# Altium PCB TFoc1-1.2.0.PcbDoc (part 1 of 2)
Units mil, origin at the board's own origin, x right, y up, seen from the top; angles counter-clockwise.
Board outline 1584.83 x 1584.83 mil, 4 copper layers (Top Layer, GND, SIGNAL, Bottom Layer), stack 61.85 mil thick; 89 components, 88 nets, 364 pads, 205 vias.
Unrouted connection lines stored in the file: 1.
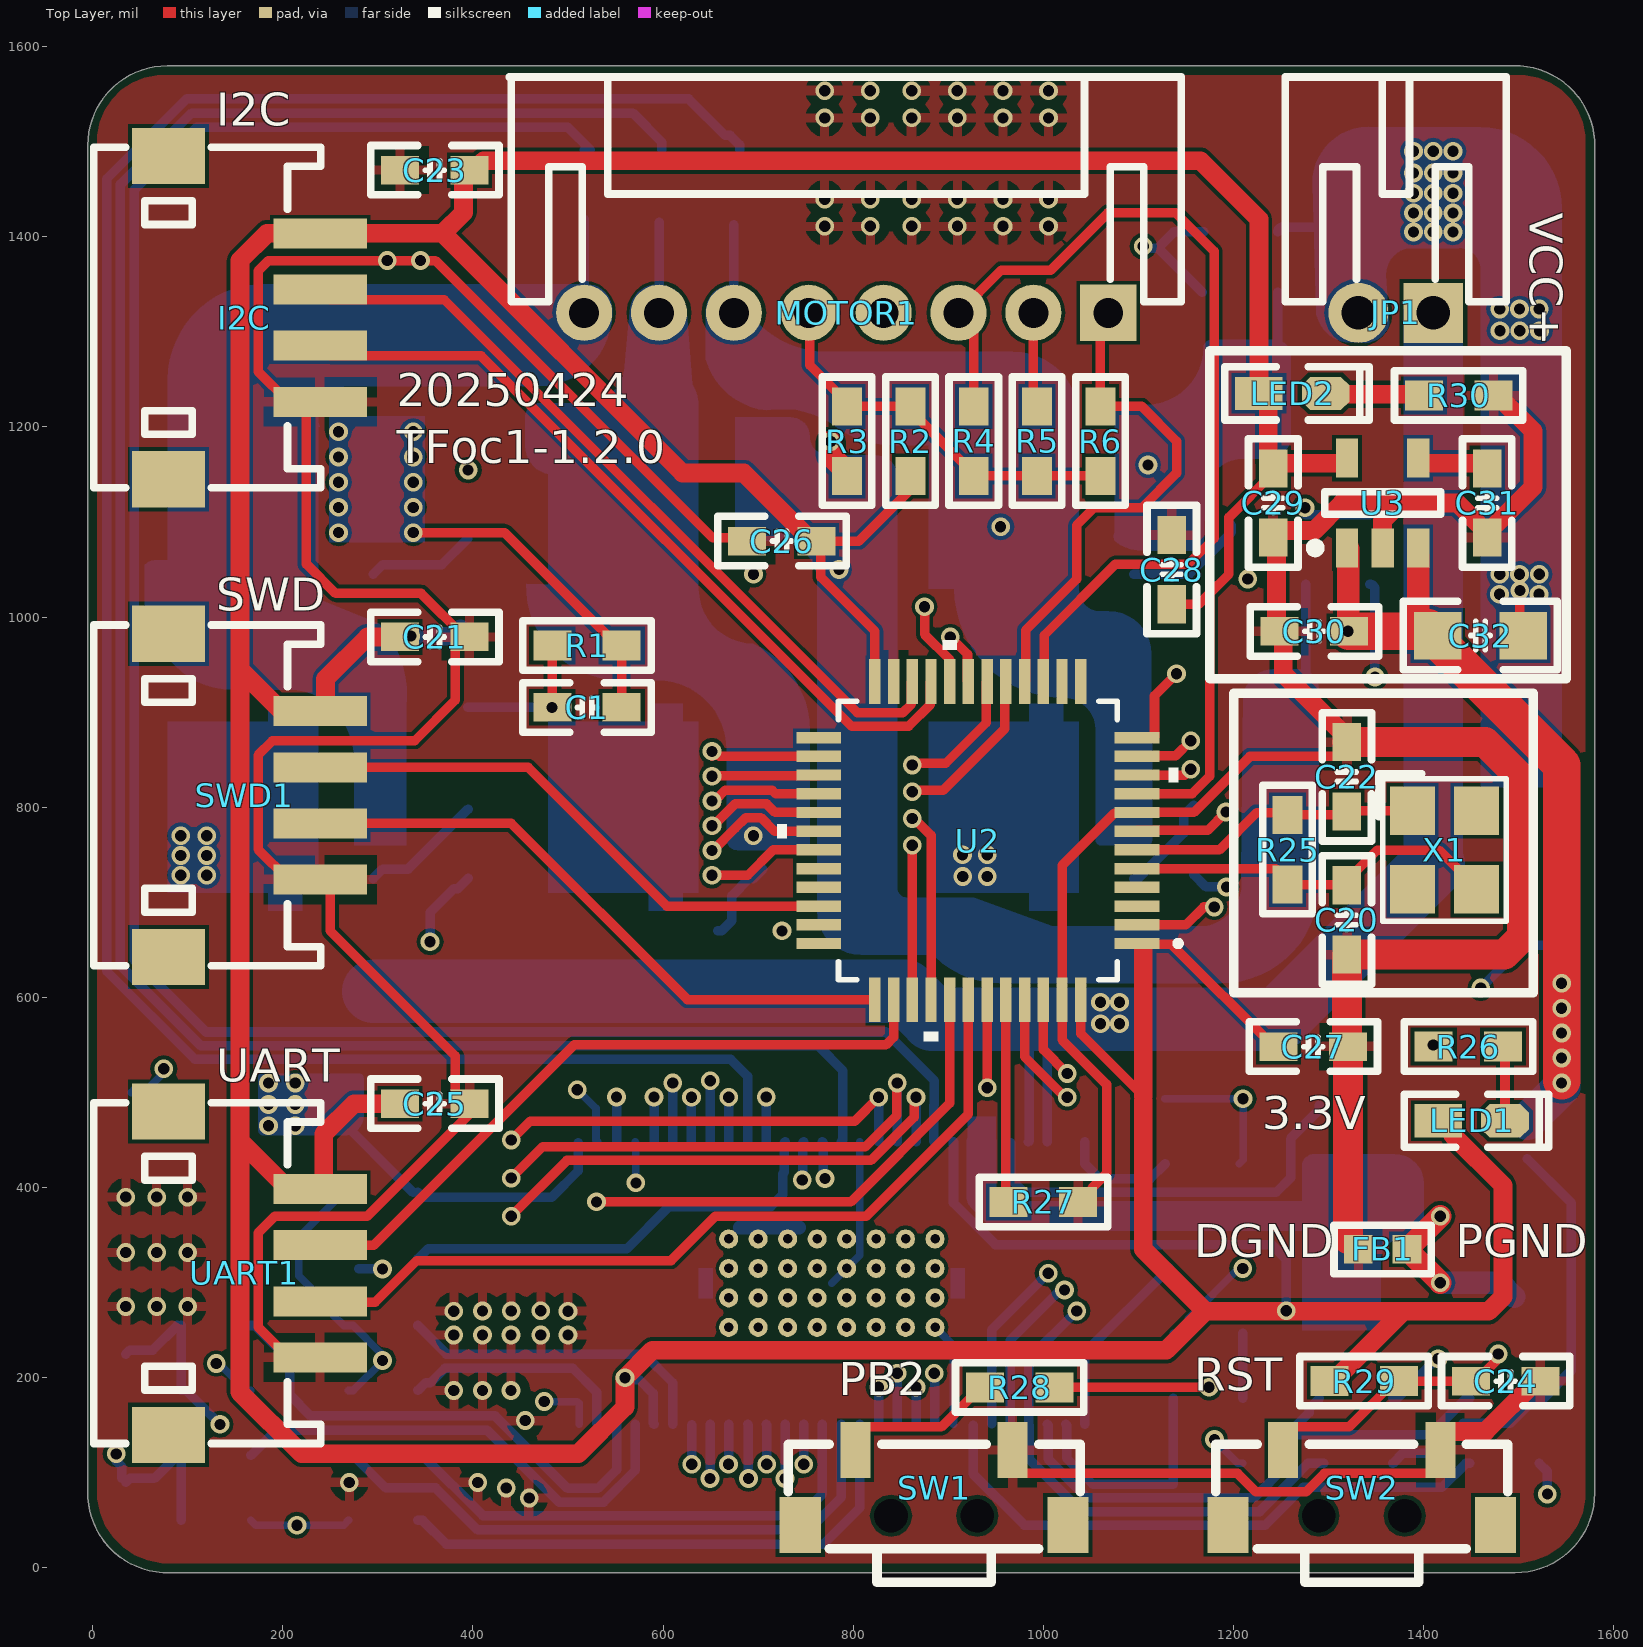
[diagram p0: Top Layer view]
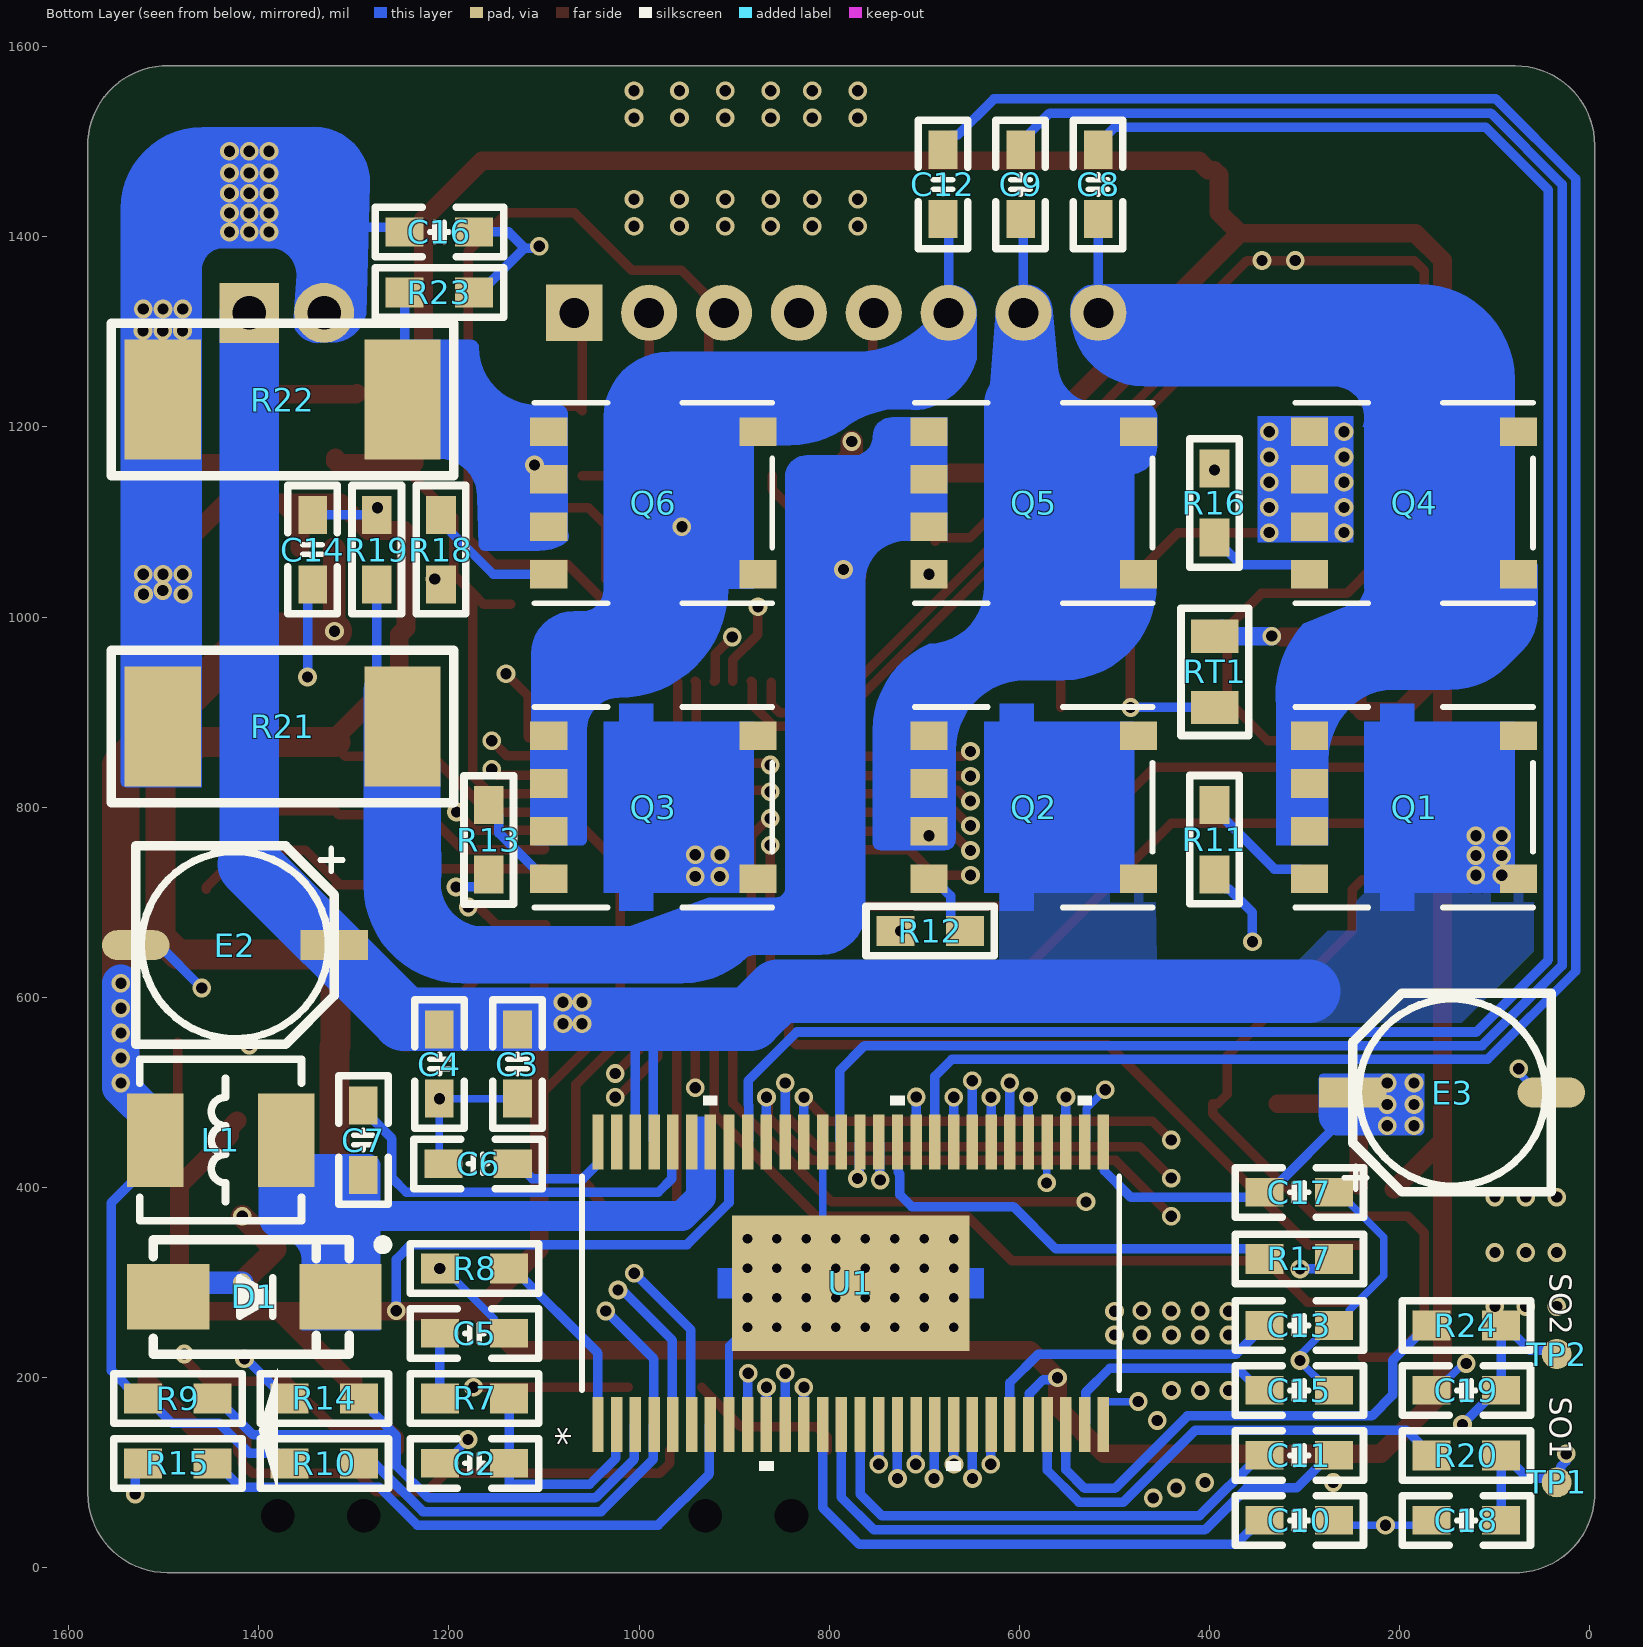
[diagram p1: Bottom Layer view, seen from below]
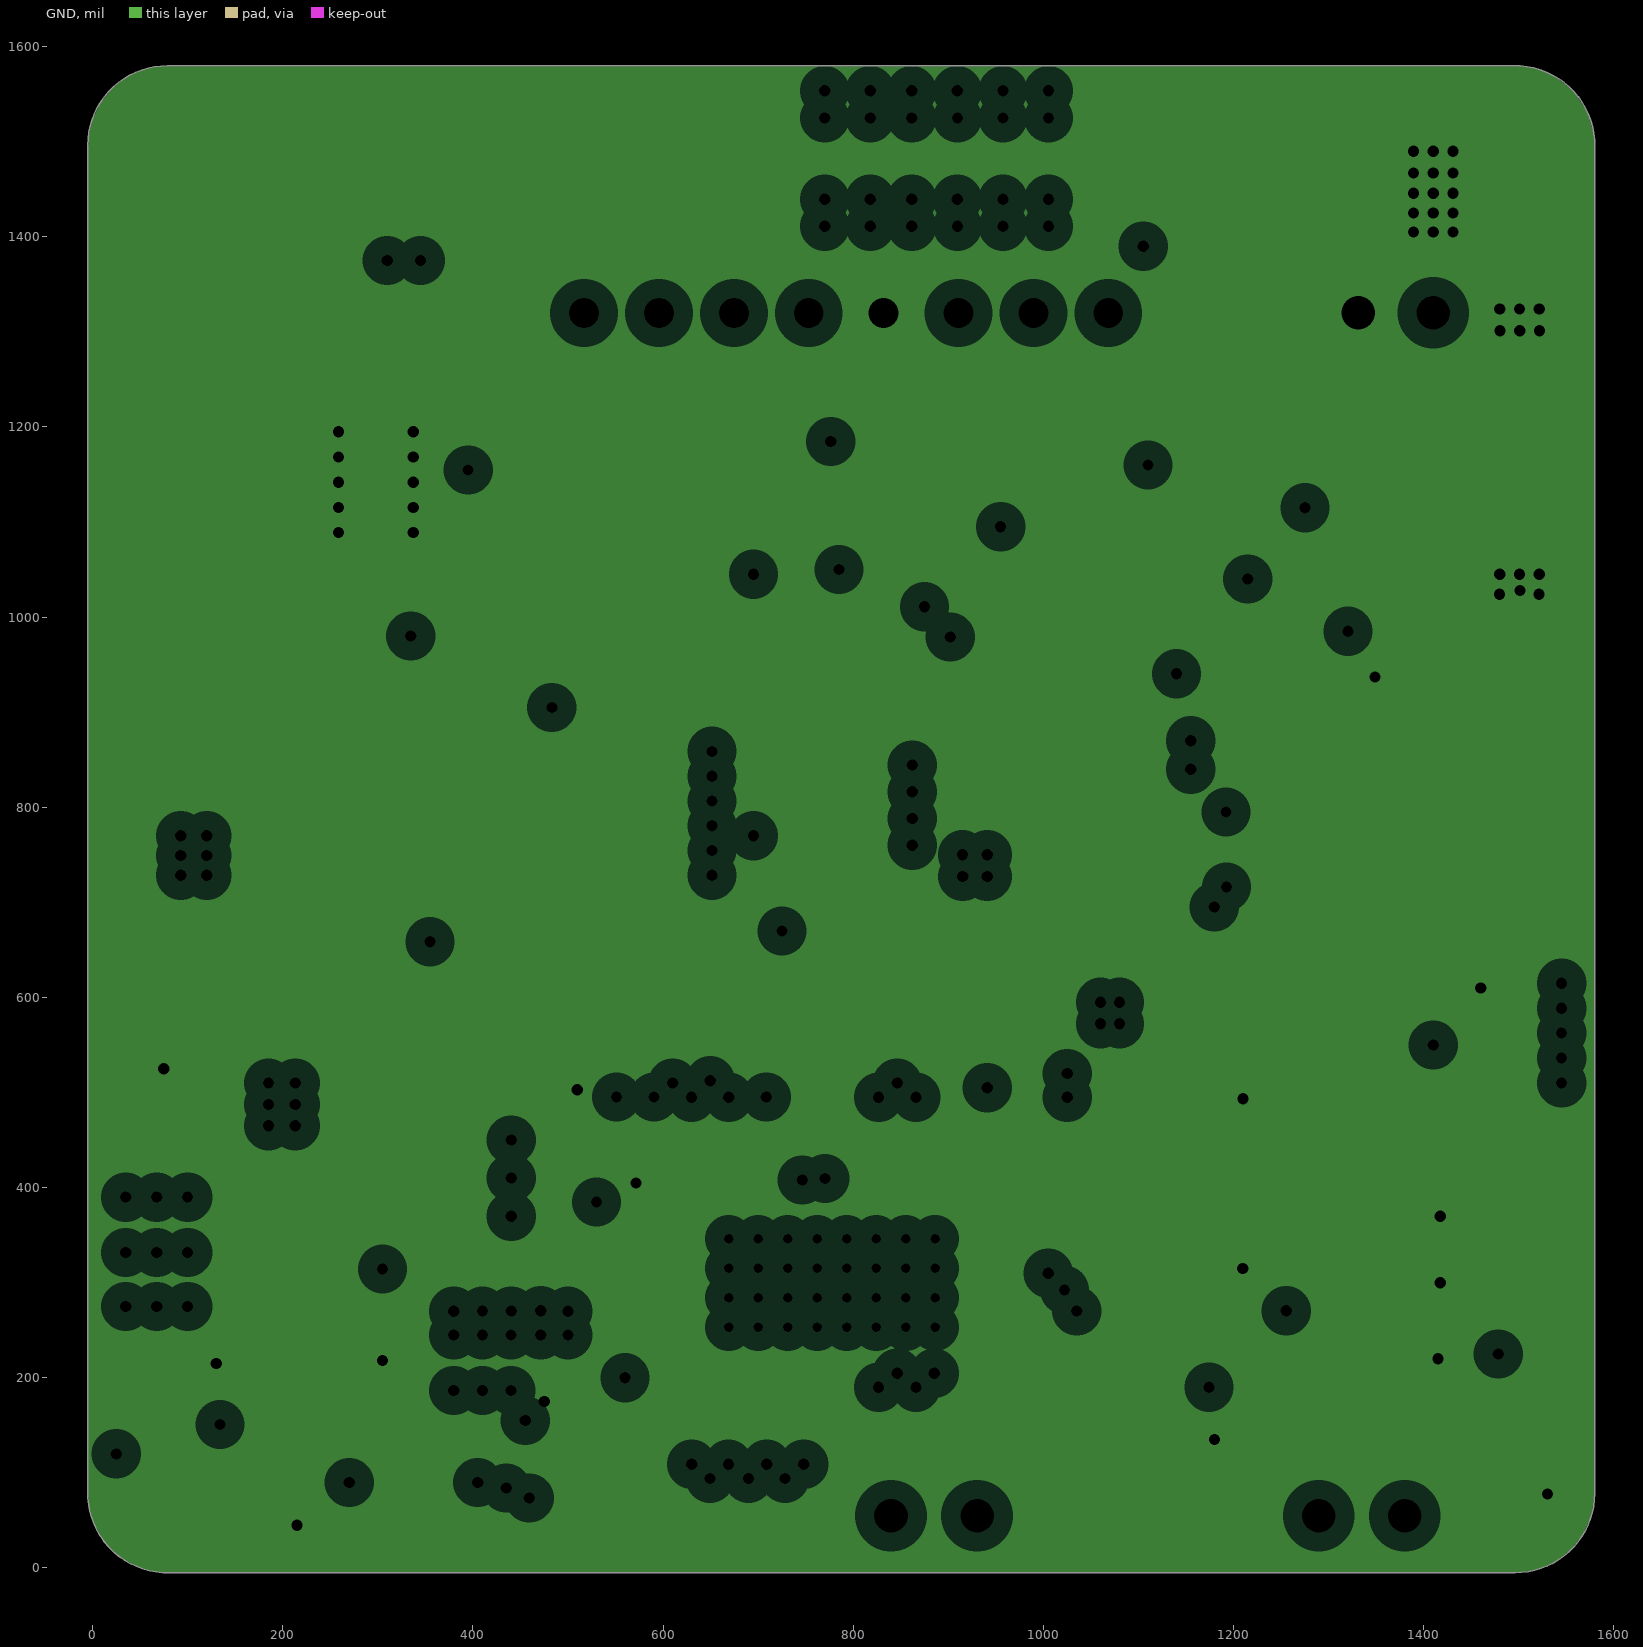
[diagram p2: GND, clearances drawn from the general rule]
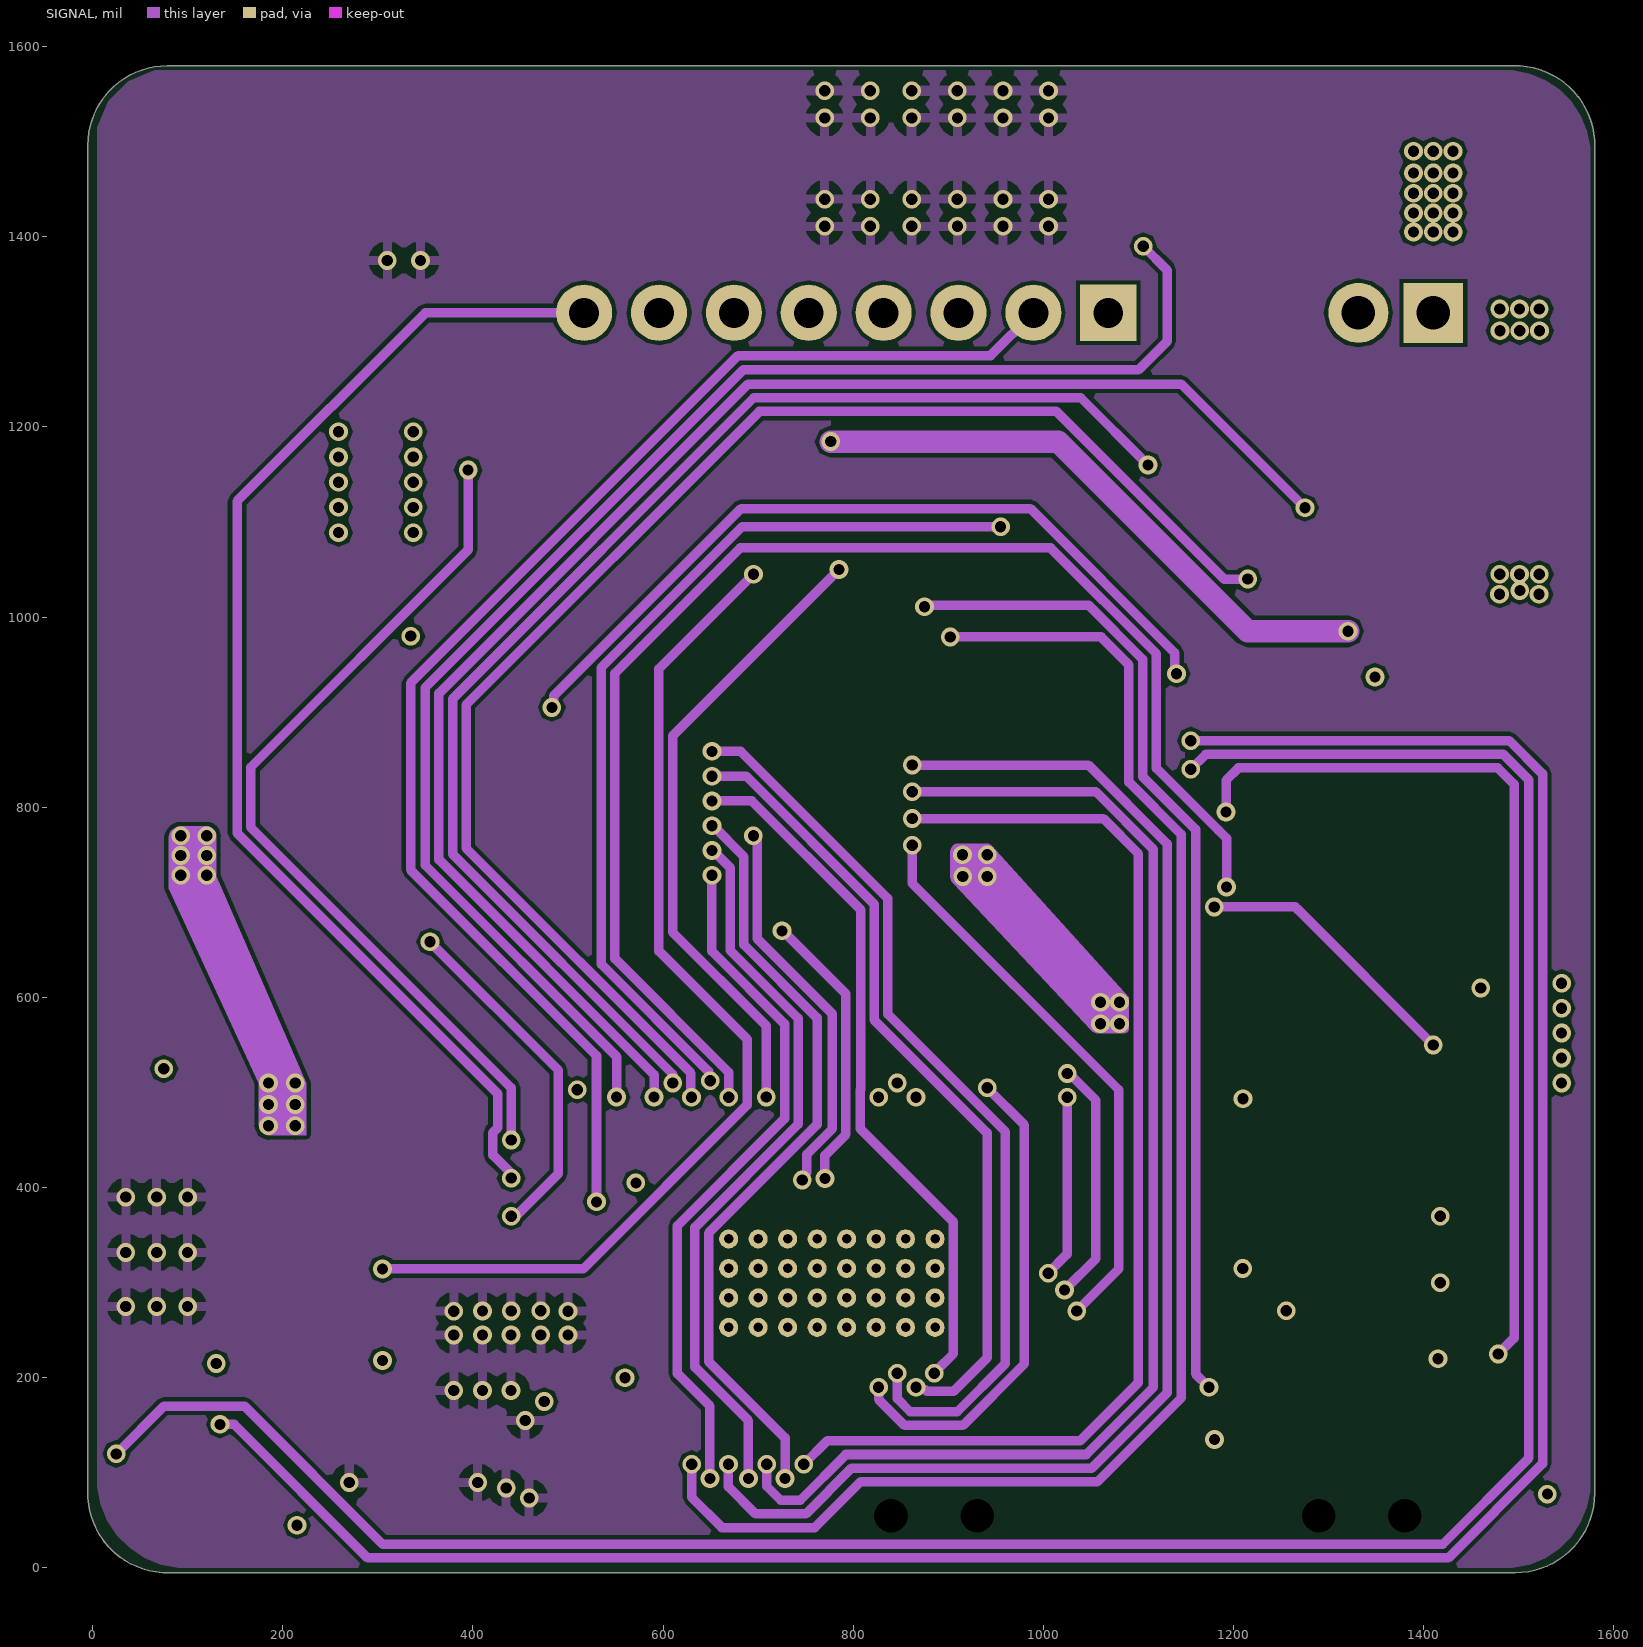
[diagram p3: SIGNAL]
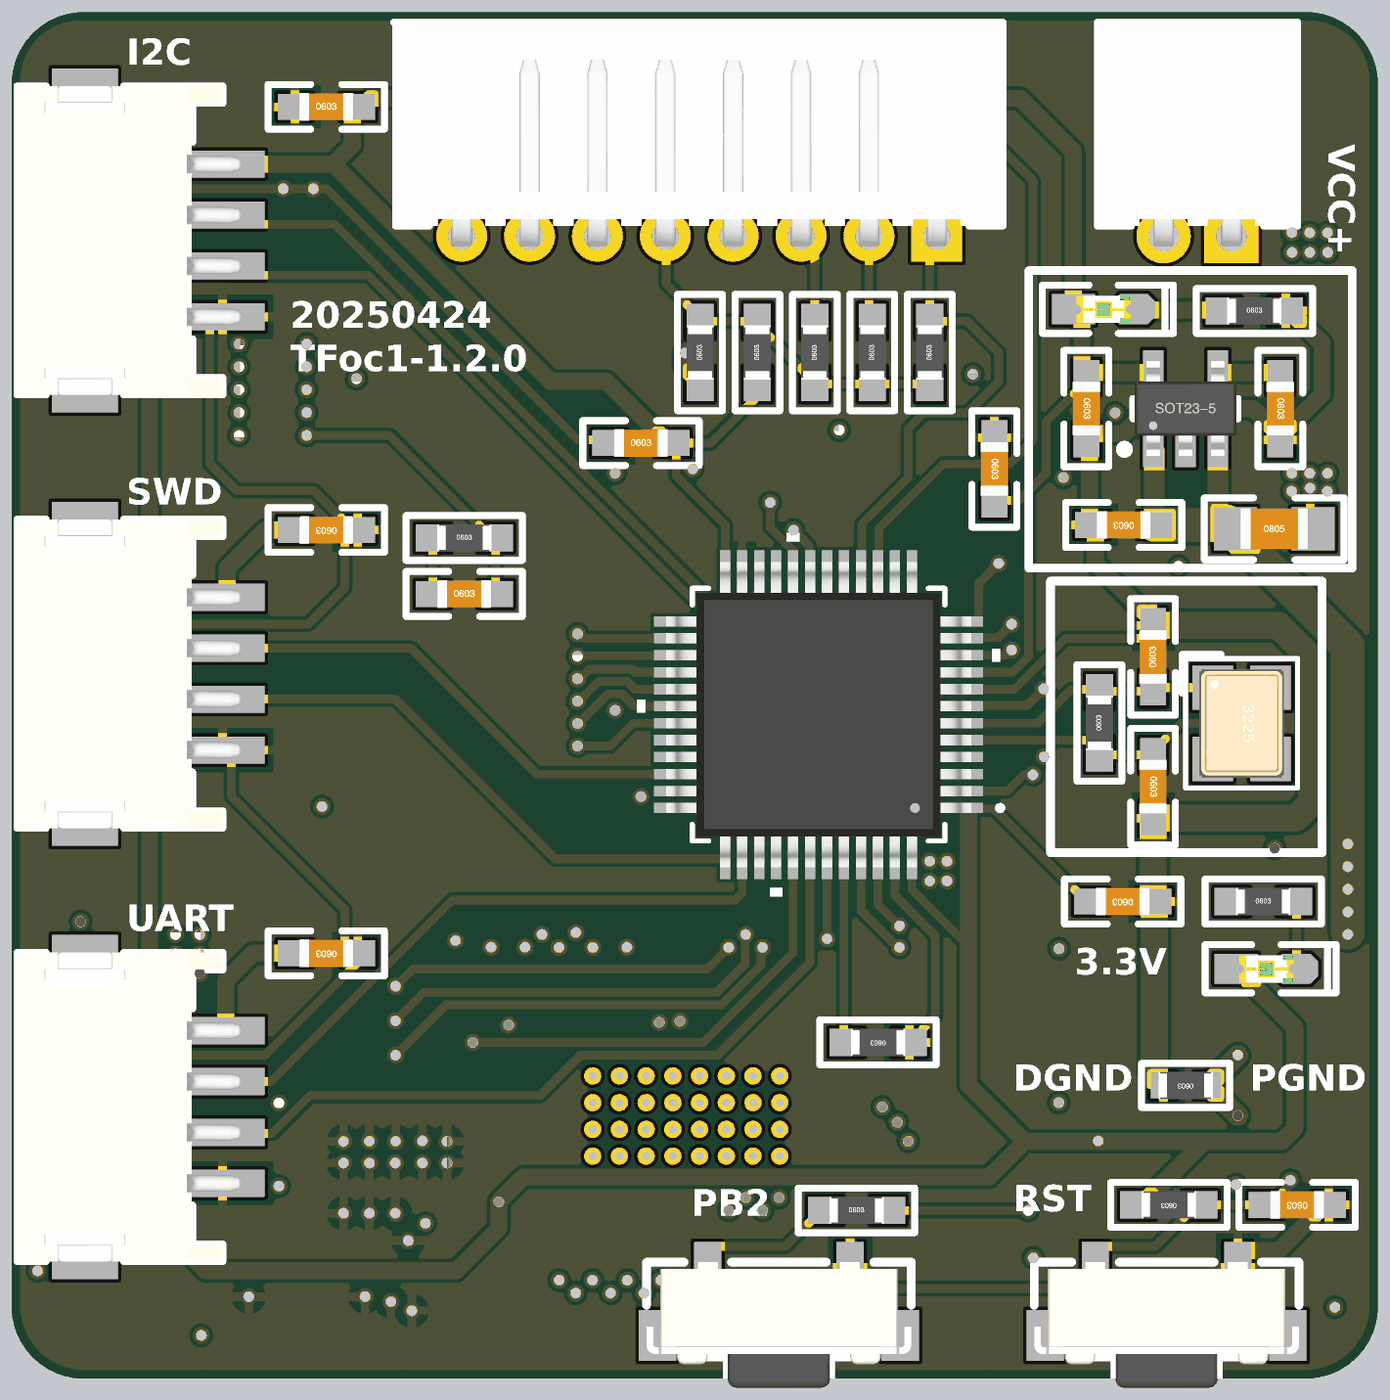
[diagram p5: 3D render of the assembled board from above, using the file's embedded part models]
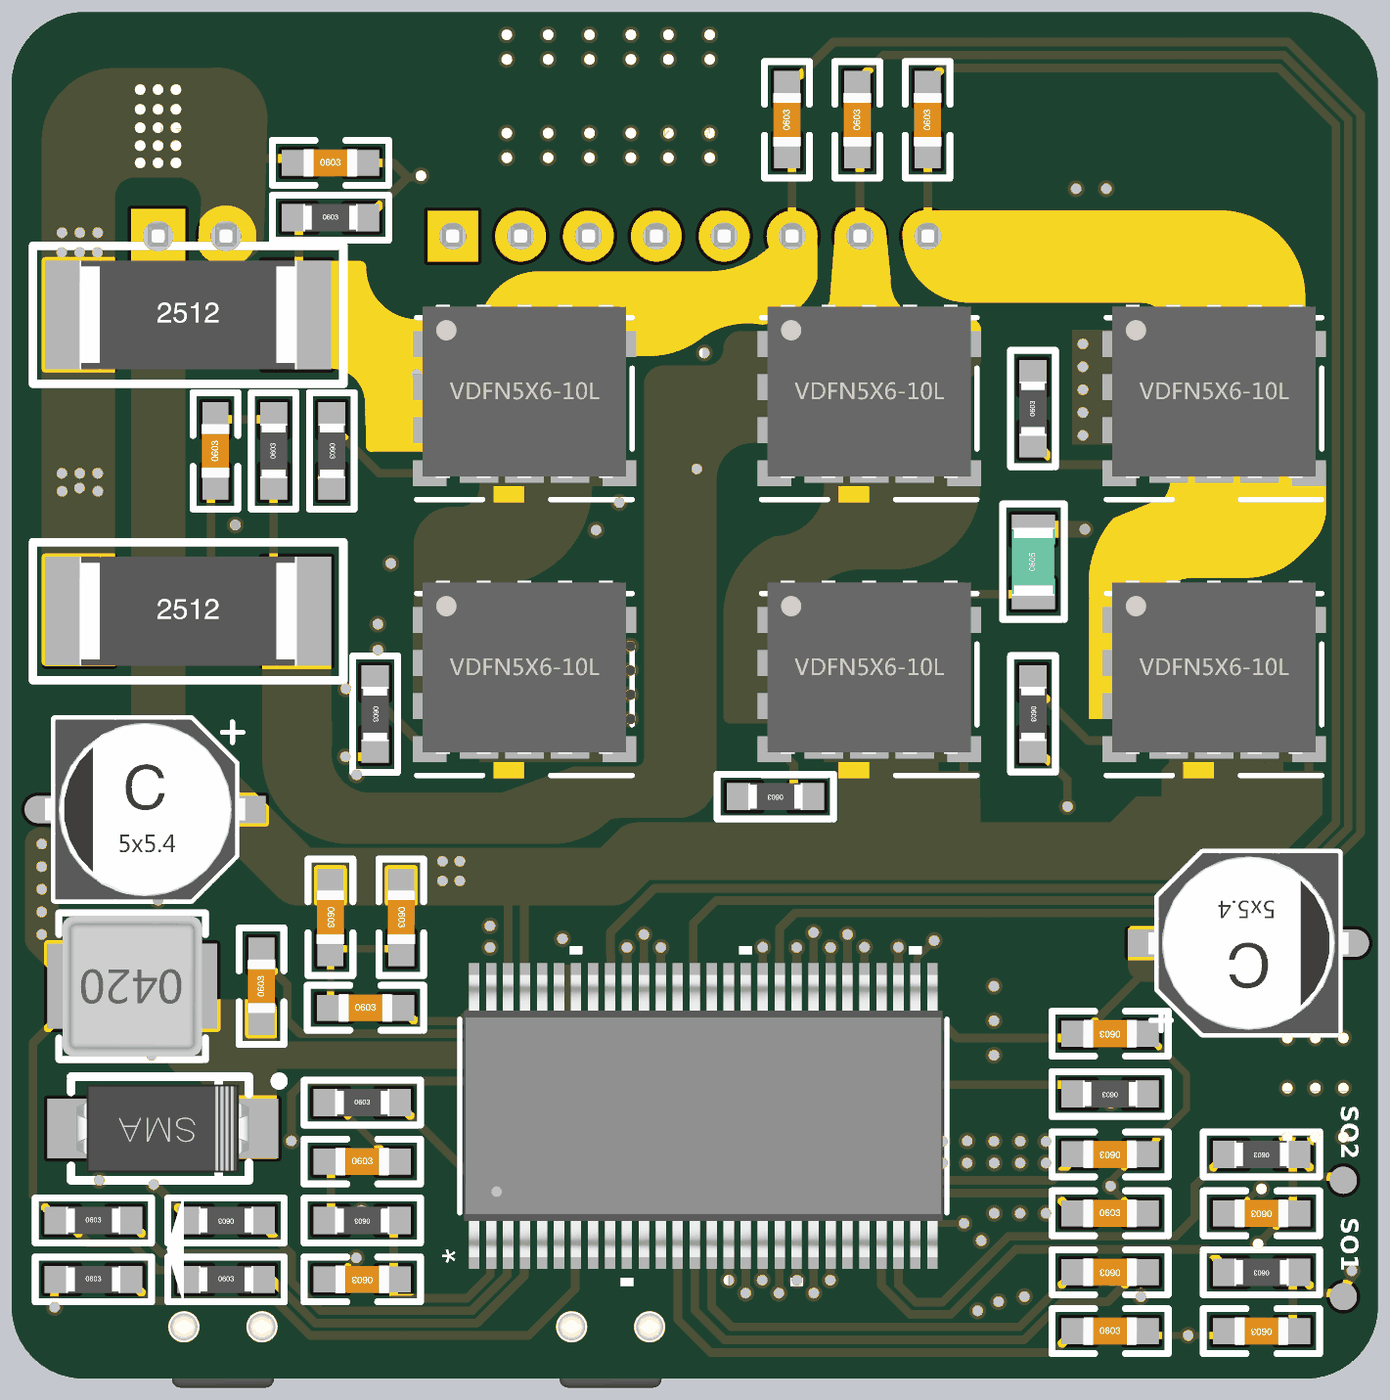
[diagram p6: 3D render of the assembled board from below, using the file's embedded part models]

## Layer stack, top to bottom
Top Solder: solder mask 0.4, Solder Resist, Dk 3.5
Top Layer: signal copper 1.3778
Dielectric 3: prepreg 7.874, PP-JLC7628, Dk 4.5
GND: plane copper 0.7086, net GND
Dielectric 1: core 41.9291, Core-JLC7628, Dk 4.6
SIGNAL: signal copper 0.7086
Dielectric 2: prepreg 7.874, PP-JLC7628, Dk 4.5
Bottom Layer: signal copper 1.3778
Bottom Solder: solder mask 0.4, Solder Resist, Dk 3.5

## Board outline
73.8,-4.87 cw(c78.74,78.74) -4.87,73.8 cw(c0,75) -5.02,75 -5.02,1496.06 cw(c78.74,1496.06) 78.74,1579.82 cw(c78.74,1574.8) 78.77,1579.82 1500.2,1579.82 cw(c1500.2,1574.8) 1501.52,1579.64 cw(c1496.06,1496.06) 1579.64,1501.52 cw(c1574.8,1500.2) 1579.82,1500.2 1579.82,78.74 cw(c1496.06,78.74) 1496.06,-5.01 75,-5.01 cw(c75,0)

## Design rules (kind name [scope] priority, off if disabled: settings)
Clearance [All] p1: gap=4 ignorepadtopadclearanceinfootprint=TRUE
PlaneClearance [All] p1: clearance=20
PlaneConnect [All] p1: planeconnectstyle=Direct reliefexpansion=5 reliefentries=4 reliefconductorwidth=10 reliefairgap=5
PolygonConnect [All] p1: connectstyle=Relief reliefconductorwidth=10 reliefentries=4 polygonreliefangle="90 Angle" airgapwidth=10
RoutingVias [All] p1: holewidth=11.81 width=19.68 viastyle="Through Hole" minholewidth=7.87 minwidth=17.72 maxholewidth=11.81 maxwidth=19.68
ShortCircuit [All] p1: allowed=TRUE
SolderMaskExpansion [All] p1: expansion=4
UnRoutedNet [All] p1: checkbadconnections=TRUE
Width [All] p1: maxlimit=196.85 minlimit=0.39 preferedwidth=10
26 further rules are at their usual default settings.

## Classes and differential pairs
component class U_POWER: C29 C30 C31 FB1 JP1 LED2 R30 U3
component class MAIN: I2C
component class U_STM32F031C6T6: C20 C21 C22 C23 C24 C25 C26 C27 C28 LED1 R25 R26 R27 R28 R29 SW1 SW2 SWD1 U2 UART1 X1
component class U_MOTOR: C1 C2 C3 C4 C5 C6 C7 C8 C9 C10 C11 C12 C13 C14 C15 C16 C17 C18 C19 C32 D1 E2 E3 L1 MOTOR1 Q1 Q2 Q3 Q4 Q5 Q6 R1 R2 R3 R4 R5 R6 R7 R8 R9 R10 R11 R12 R13 R14 R15 R16 R17 R18 R19 R20 R21 R22 R23 R24 RT1 TP1 TP2 U1

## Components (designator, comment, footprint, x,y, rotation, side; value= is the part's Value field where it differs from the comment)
C1 "2.2uF" C0603_M 520,905 r0 top
C2 "82pF" C0603_M 1173.09,110 r0 bottom
C3 "68nF" C0603_M 1127.89,530 r270 bottom
C4 "4.7uF" C0603_M 1210,530 r270 bottom
C5 "270pF" C0603_M 1173.09,246.67 r180 bottom
C6 "6.8nF" C0603_M 1169.39,425 r180 bottom
C7 "100nF" C0603_M 1290,450 r90 bottom
C8 "100nF" C0603_M 517.27,1455 r90 bottom
C9 "100nF" C0603_M 598.84,1455 r90 bottom
C10 "2.2uF" C0603_M 305.68,50 r180 bottom
C11 "22nF" C0603_M 305.68,118.33 r0 bottom
C12 "100nF" C0603_M 680.41,1455 r90 bottom
C13 "2.2uF" C0603_M 305.68,255 r0 bottom
C14 "2.2nF" C0603_M 1343.42,1070.94 r90 bottom
C15 "2.2uF" C0603_M 305.68,186.67 r180 bottom
C16 "2.2nF" C0603_M 1210.02,1405 r180 bottom
C17 "68nF" C0603_M 305.68,395 r0 bottom
C18 "2.2uF" C0603_M 130,50 r0 bottom
C19 "2.2uF" C0603_M 130,186.67 r0 bottom
C20 "20pF" C0603_M 1319.06,681.5 r270 top
C21 "100nF" C0603_M 360,979.13 r180 top
C22 "20pF" C0603_M 1319.06,832.01 r90 top
C23 "100nF" C0603_M 360,1470 r0 top
C24 "1uF" C0603_M 1486.19,196.42 r180 top
C25 "100nF" C0603_M 360,488.26 r180 top
C26 "100nF" C0603_M 725,1080 r0 top
C27 "100nF" C0603_M 1283.85,548.26 r180 top
C28 "100nF" C0603_M 1135,1050 r270 top
C29 "1uF" C0603_M 1241.69,1120 r270 top
C30 "1nF" C0603_M 1285,985 r180 top
C31 "22nF" C0603_M 1466.69,1120 r270 top
C32 "100nF" C0805_M 1459.56,980.57 r0 top
D1 "SS24" SMA 1404.57,285 r180 bottom
E2 "10uF/50V" "CE C(5*5.4)" 1425,655 r180 bottom
E3 "10uF/50V" "CE C(5*5.4)" 145,500 r0 bottom
FB1 "0R" R0603_L 1356.79,335 r180 top
I2C "HDR-1X4" ZH1.5-WS-4P 80,1315 r270 top
JP1 "HDR-1X2" PH2.0-W-2P 1370.63,1320 r180 top
L1 "22uH" L-SMD-0420 1440,450 r0 bottom
LED1 "蓝色" LED0603_B 1450.43,470 r0 top
LED2 "红色" LED0603_R 1261.69,1235 r0 top
MOTOR1 "HDR-1X8" PH2.0-W-8P 792.6,1320 r180 top
Q1 "MOSFET-N" DFN5_5X6_ONS 185,800 r180 bottom
Q2 "MOSFET-N" DFN5_5X6_ONS 585,800 r180 bottom
Q3 "MOSFET-N" DFN5_5X6_ONS 985,800 r180 bottom
Q4 "MOSFET-N" DFN5_5X6_ONS 185,1120 r180 bottom
Q5 "MOSFET-N" DFN5_5X6_ONS 585,1120 r180 bottom
Q6 "MOSFET-N" DFN5_5X6_ONS 985,1120 r180 bottom
R1 "3.3K" R0603_M 520,970 r0 top
R2 "0R" R0603_M 860.14,1185 r90 top
R3 "0R" R0603_M 793.52,1185 r90 top
R4 "120R" R0603_M 926.76,1185 r90 top
R5 "120R" R0603_M 993.38,1185 r90 top
R6 "120R" R0603_M 1060,1185 r90 top
R7 "47K" R0603_M 1173.09,178.33 r0 bottom
R8 "220k" R0603_M 1173.09,315 r180 bottom
R9 "18K" R0603_M 1485,178.33 r180 bottom
R10 "10K" R0603_M 1331.07,110 r180 bottom
R11 "2.2R" R0603_M 395,765.89 r270 bottom
R12 "2.2R" R0603_M 693.85,670 r0 bottom
R13 "2.2R" R0603_M 1158.14,765.72 r270 bottom
R14 "3.3K" R0603_M 1331.07,178.33 r0 bottom
R15 "18K" R0603_M 1485,110 r180 bottom
R16 "2.2R" R0603_M 395,1120 r90 bottom
R17 "2.2R" R0603_M 305.68,325 r0 bottom
R18 "2.2R" R0603_M 1208.42,1070.94 r270 bottom
R19 "120R" R0603_M 1275.92,1070.94 r90 bottom
R20 "22R" R0603_M 130,118.33 r0 bottom
R21 "500uOhm" R2512_M 1375,885 r180 bottom
R22 "500uOhm" R2512_M 1375,1228.79 r180 bottom
R23 "120R" R0603_M 1210.02,1341.39 r180 bottom
R24 "22R" R0603_M 130,255 r0 bottom
R25 "1M" R0603_M 1256.82,755.47 r90 top
R26 "10K" R0603_M 1446.94,548.26 r0 top
R27 "10K" R0603_M 1000,385 r180 top
R28 "10K" R0603_M 975,190 r0 top
R29 "10K" R0603_M 1337.26,196.42 r180 top
R30 "1K" R0603_M 1436.69,1233.26 r0 top
RT1 "10K" R0805-HP_L 394.72,942.37 r90 bottom
SW1 "3x6x5" "SW 3*6*4.3-S-W" 885,55 r0 top
SW2 "3x6x5" "SW 3*6*4.3-S-W" 1334.72,55 r0 top
SWD1 "HDR-1X4" ZH1.5-WS-4P 80,812.5 r270 top
TP1 "SO1" "TEST 0.8" 35,90 r90 bottom
TP2 "SO2" "TEST 0.8" 35,225 r90 bottom
U1 "DRV8301DCA" DRV8301DCA 777.5,299.5 r90 bottom
U2 "STM32F031C6T6" LQFP48-7x7mm 931.01,765 r180 top
U3 "RT9193-30GB" SOT-23-5 1356.69,1120 r90 top
UART1 "HDR-1X4" ZH1.5-WS-4P 80,310 r270 top
X1 "8M" XTAL-3225-4P 1421.82,755 r270 top

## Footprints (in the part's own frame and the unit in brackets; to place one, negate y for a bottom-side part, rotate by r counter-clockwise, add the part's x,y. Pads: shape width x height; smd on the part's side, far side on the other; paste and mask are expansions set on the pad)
C0603_M [mil]
  rect 40x30 smd: 1(-36.5,0) 2(36.5,0)
  silkscreen extent -68,-26 68,26, body extent -31,-16 31,16, height 33
C0805_M [mil] "贴片MLCC电容"
  rect 50x50 smd: 1(-45,0) 2(45,0)
  silkscreen extent -81,-36 81,36, body extent -39,-24 39,24, height 22
"CE C(5*5.4)" [mm] "贴片电解电容，直径5mm，高5.4mm            联系卖家 免费查找封装"
  rect 1.8x0.8 smd: 1(2.65,0)
  oval 1.8x0.8 smd: 2(-2.65,0)
  silkscreen extent -2.65,-2.65 2.88,2.65, body extent -2.95,-2.65 2.95,2.65, height 5.48
DFN5_5X6_ONS [mil]
  rect 39x30 smd paste+0 mask+0: D(110.04,-75) D(110.04,75) G(-110.04,-75) S(-110.04,-25) S(-110.04,25) S(-110.04,75)
  Top Layer region: 0,-90 -35.63,-90 -35.63,-90 -35.63,-90 -35.63,-109 0,-109 0,-90 0,-90
  Top Layer region: 0,90 -35.63,90 -35.63,90 -35.63,90 -35.63,109 0,109 0,90 0,90
  Top Layer region: 105.77,90 -52.23,90 -52.23,-90 105.77,-90
  silkscreen extent -125,-106 125,106, body extent -118,-80 118,120, height 42
DRV8301DCA [mil]
  rect 57.56x12 smd paste+0 mask+0: 1(-148.5,265.75) 2(-148.5,246.06) 3(-148.5,226.38) 4(-148.5,206.69) 5(-148.5,187.01) 6(-148.5,167.32) 7(-148.5,147.64) 8(-148.5,127.95) 9(-148.5,108.27) 10(-148.5,88.58) 11(-148.5,68.9) 12(-148.5,49.21) 13(-148.5,29.53) 14(-148.5,9.84) 15(-148.5,-9.84) 16(-148.5,-29.53) 17(-148.5,-49.21) 18(-148.5,-68.9) 19(-148.5,-88.58) 20(-148.5,-108.27) 21(-148.5,-127.95) 22(-148.5,-147.64) 23(-148.5,-167.32) 24(-148.5,-187.01) 25(-148.5,-206.69) 26(-148.5,-226.38) 27(-148.5,-246.06) 28(-148.5,-265.75) 29(148.5,-265.75) 30(148.5,-246.06) 31(148.5,-226.38) 32(148.5,-206.69) 33(148.5,-187.01) 34(148.5,-167.32) 35(148.5,-147.64) 36(148.5,-127.95) 37(148.5,-108.27) 38(148.5,-88.58) 39(148.5,-68.9) 40(148.5,-49.21) 41(148.5,-29.53) 42(148.5,-9.84) 43(148.5,9.84) 44(148.5,29.53) 45(148.5,49.21) 46(148.5,68.9) 47(148.5,88.58) 48(148.5,108.27) 49(148.5,127.95) 50(148.5,147.64) 51(148.5,167.32) 52(148.5,187.01) 53(148.5,206.69) 54(148.5,226.38) 55(148.5,246.06) 56(148.5,265.75)
  rect 142.13x250 smd paste-124.5 mask-124.5: 57(0,0)
  round 20 hole 10: V(-46.5,-108.5) V(-46.5,-77.5) V(-46.5,-46.5) V(-46.5,-15.5) V(-46.5,15.5) V(-46.5,46.5) V(-46.5,77.5) V(-46.5,108.5) V(-15.5,-108.5) V(-15.5,-77.5) V(-15.5,-46.5) V(-15.5,-15.5) V(-15.5,15.5) V(-15.5,46.5) V(-15.5,77.5) V(-15.5,108.5) V(15.5,-108.5) V(15.5,-77.5) V(15.5,-46.5) V(15.5,-15.5) V(15.5,15.5) V(15.5,46.5) V(15.5,77.5) V(15.5,108.5) V(46.5,-108.5) V(46.5,-77.5) V(46.5,-46.5) V(46.5,-15.5) V(46.5,15.5) V(46.5,46.5) V(46.5,77.5) V(46.5,108.5)
  Top Layer region: 15.75,-125 -15.75,-125 -15.75,-125 -15.75,-125 -15.75,-139.96 15.75,-139.96 15.75,-125 15.75,-125
  Top Layer region: 15.75,125 -15.75,125 -15.75,125 -15.75,125 -15.75,139.96 15.75,139.96 15.75,125 15.75,125
  silkscreen extent -197,-282 197,282, body extent -164,-277 164,277, height 67
L-SMD-0420 [mm]
  rect 1.5x2.5 smd: 1(-1.75,0) 2(1.75,0)
  silkscreen extent -2.16,-2.16 2.16,2.16, body extent -2.25,-2.05 2.25,2.05
LED0603_B [mil] "蓝色0603LED"
  rect 50x35 smd: 1(-35,0.26)
  oct 50x35 smd: 2(35,0.26)
  silkscreen extent -71,-28 81,28, body extent -32,-16 31,16, height 18
LED0603_R [mil] "红色0603LED"
  rect 50x35 smd: 1(-35,0.26)
  oct 50x35 smd: 2(35,0.26)
  silkscreen extent -71,-28 81,28, body extent -32,-16 31,16, height 18
LQFP48-7x7mm [mil]
  rect 47x12 smd paste+0 mask+0: 1(-167.32,108.27) 2(-167.32,88.58) 3(-167.32,68.9) 4(-167.32,49.21) 5(-167.32,29.53) 6(-167.32,9.84) 7(-167.32,-9.84) 8(-167.32,-29.53) 9(-167.32,-49.21) 10(-167.32,-68.9) 11(-167.32,-88.58) 12(-167.32,-108.27) 25(167.32,-108.27) 26(167.32,-88.58) 27(167.32,-68.9) 28(167.32,-49.21) 29(167.32,-29.53) 30(167.32,-9.84) 31(167.32,9.84) 32(167.32,29.53) 33(167.32,49.21) 34(167.32,68.9) 35(167.32,88.58) 36(167.32,108.27)
  rect 12x47 smd paste+0 mask+0: 13(-108.27,-167.32) 14(-88.58,-167.32) 15(-68.9,-167.32) 16(-49.21,-167.32) 17(-29.53,-167.32) 18(-9.84,-167.32) 19(9.84,-167.32) 20(29.53,-167.32) 21(49.21,-167.32) 22(68.9,-167.32) 23(88.58,-167.32) 24(108.27,-167.32) 37(108.27,167.32) 38(88.58,167.32) 39(68.9,167.32) 40(49.21,167.32) 41(29.53,167.32) 42(9.84,167.32) 43(-9.84,167.32) 44(-29.53,167.32) 45(-49.21,167.32) 46(-68.9,167.32) 47(-88.58,167.32) 48(-108.27,167.32)
  silkscreen extent -214,-211 211,211, body extent -177,-177 177,177, height 63
PH2.0-W-2P [mm] "长：5.9mm，宽：6mm，高：4.7mm"
  rect 1.6x1.6 hole 0.9: 1(-1,0)
  round 1.6 hole 0.9: 2(1,0)
  silkscreen extent -2.95,-6.3 2.95,-0.3, body extent -2.95,-6.3 2.95,0.3, height 4.75
PH2.0-W-8P [mm] "长：17.9mm，宽：6mm，高：4.7mm     淘宝ID:黄晶宝石"
  rect 1.5x1.5 hole 0.8: 1(-7,0)
  round 1.5 hole 0.8: 2(-5,0) 3(-3,0) 4(-1,0) 5(1,0) 6(3,0) 7(5,0) 8(7,0)
  silkscreen extent -8.95,-6.3 9,-0.3, body extent -8.95,-6.3 8.95,0.3, height 4.75
R0603_L [mil] "1/10W贴片电阻"
  rect 30x30 smd: 1(-25.59,0) 2(25.59,0)
  silkscreen extent -51,-26 51,26, body extent -31,-16 32,16, height 16
R0603_M [mil]
  rect 40x31.5 smd: 1(-36.5,0) 2(36.5,0)
  silkscreen extent -68,-26 68,26, body extent -31,-16 31,16, height 16
R0805-HP_L [mil]
  rect 35x50 smd: 1(-37.4,0) 2(37.4,0)
  silkscreen extent -67,-36 67,35, body extent -39,-25 39,25, height 20
R2512_M [mm]
  rect 2.032x3.2 smd: 1(-3.2,0) 2(3.2,0)
  silkscreen extent -4.57,-2.03 4.57,2.03, body extent -3.2,-1.6 3.2,1.6, height 0.55
SMA [mm] "4.5x2.6*2.2mm（长宽高，不包括引脚）联系卖家 免?"
  rect 2.2x1.75 smd: 1(-2.3,0) 2(2.3,0)
  silkscreen extent -2.7,-1.52 3.56,1.52, body extent -2.55,-1.3 2.55,1.3, height 2.15
SOT-23-5 [mm] "SOT23, 5-Leads, Body 2.9x1.6mm, Pitch 0.95mm, IPC Medium Density"
  rect 1.05x0.6 smd: 1(-1.2,0.95) 2(-1.2,0) 3(-1.2,-0.95) 4(1.2,-0.95) 5(1.2,0.95)
  silkscreen extent -1.32,-1.55 0.3,1.92, body extent -1.4,-1.5 1.4,1.5, height 1.15
"SW 3*6*4.3-S-W" [mm] "侧立贴片3*6*4.3"
  rect 1.1x1.5 smd: 0(-3.575,-0.25) 0(3.575,-0.25)
  round 0 hole 0.9: 0(-1.15,0) 0(1.15,0)
  rect 0.8x1.5 smd: 1(2.1,1.75) 2(-2.1,1.75)
  silkscreen extent -3.9,-1.78 3.9,1.91, body extent -3.9,-1.79 3.9,1.91, height 3.51
"TEST 0.8" [mm] "?"
  round 0.8 smd: 1(0,0)
XTAL-3225-4P [mm] "3.2*2.5*0.7mm(长宽?"
  rect 1.3x1.2 smd: 1(-1.05,-0.85) 2(1.05,-0.85) 3(1.05,0.85) 4(-1.05,0.85)
  silkscreen extent -2.03,-1.75 1.91,1.65, body extent -1.6,-1.25 1.6,1.25, height 0.7
ZH1.5-WS-4P [mm] "长：9.1mm，宽：6.0mm，高：3.7mm淘宝ID:黄晶宝石   店铺网址:https://shop463601444.taobao.com"
  rect 1.5x1.95 smd: 0(-4.318,0) 0(4.318,0)
  rect 0.8x2.5 smd: 1(-2.25,4.05) 2(-0.75,4.05) 3(0.75,4.05) 4(2.25,4.05)
  silkscreen extent -4.55,-2 4.55,4.06, body extent -4.55,-2 4.55,4.6, height 3.75

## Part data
C1 C2 C3 C4 C5 C6 C7 C8 C9 C10 C11 C12 C13 C14 C15 C16 C17 C18 C19 C20 C21 C22 C23 C24 C25 C26 C27 C28 C29 C30 C31: library part C, "贴片"
C32: library part C, "贴片电容/MLCC电容"
D1: library part 1N4007, "整流二极管"
E2 E3: library part CE_SMD, "贴片电解电容"
FB1: library part R, "贴片电阻"
I2C SWD1 UART1: library part "Header 4", "4P接插件"
JP1: library part "Header 2", "2P接插件"
L1: library part "L-Molding Choke"
LED1 LED2: library part LED-SMD, "贴片LED"
MOTOR1: library part "Header 8", "8P接插件"
Q1 Q2 Q3 Q4 Q5 Q6: "N-Channel MOSFET", PackageDocument=1995/1996
R1 R2 R3 R4 R5 R6 R7 R8 R9 R10 R11 R12 R13 R14 R15 R16 R17 R18 R19 R20 R21 R22 R23 R24 R25 R26 R27 R28 R29 R30: library part R
RT1: library part RT
SW1 SW2: library part "SW 3x6", "3x6轻触开关"
TP1 TP2: library part TEST, "测试点"
U1: "No Description Available", Mfr_Name="Texas Instruments"
U2: "No Description Available", Mfr_Name=STMicroelectronics
U3: "LDO 3.0V/0.3A"
X1: library part XTAL-4P, "4脚无源晶振(谐振器）"

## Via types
v1: diameter 19.68, hole 11.81, Top Layer to Bottom Layer, tented both sides, 205 vias

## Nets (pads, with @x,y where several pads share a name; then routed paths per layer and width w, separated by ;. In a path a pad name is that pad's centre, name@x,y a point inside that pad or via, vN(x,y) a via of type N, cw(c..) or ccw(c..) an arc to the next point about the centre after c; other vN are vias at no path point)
+3.3V: C21.2 C23.2 C25.2 C26.2 C27.2 C28.2 C29.1 I2C.1 LED1.1 LED2.1 R2.1 R29.2 RT1.2 SWD1.1 U1.24 U1.49 U2.1 U2.9 U2.24 U2.48 U3.5 UART1.1 | length 7579.7
  Top Layer w10: C26.2@756.5,1080 C26.2@761.5,1080 ; U2.24@822.74,932.32 822.74,985.14 765.83,1042.06 765.83,1075.67 C26.2@761.5,1080 ; R2.1@860.14,1148.5 860.14,1134.25 805.89,1080 C26.2@761.5,1080 ; U2.48@1039.28,597.68 1039.28,562 1105,496.28 ; U2.9@1098.33,814.21 1156.33,814.21 1174.69,832.58 1174.69,1024.69 ; U2.1@1099.33,655.73 1134.87,655.73 1242.35,548.26 C27.2@1247.35,548.26 ; C28.2@1135,1013.5 1163.5,1013.5 1174.69,1024.69 ; C29.1@1241.69,1151.5 1195,1104.81 1195,1045 1174.69,1024.69
  Top Layer w19.68: UART1.1@205.98,398.58 155,449.57 ; SWD1.1@239.45,901.08 198.92,901.08 155,945 ; UART1.1@243.25,402.38 243.25,456.51 275,488.26 C25.2@323.5,488.26 C25.2@328.5,488.26 ; SWD1.1@245,906.63 245,935 289.13,979.13 C21.2@323.5,979.13 ; C26.2@756.5,1080 685,1151.5 620.42,1151.5 368.34,1403.58 ; 1105,491.5 1105,335.26 1170.26,270 ; 1105,496.28 U2.1@1105,652.89 ; LED2.1@1226.7,1235.26 1226.7,1418.3 1165.22,1479.78 411.28,1479.78 401.5,1470 C23.2@396.5,1470 395.39,1470 390.23,1464.84 390.23,1425.47 368.34,1403.58 ; LED2.1@1228.88,1235.26 1236.54,1227.6 1236.54,1161.66 C29.1@1241.69,1156.5 1241.69,1156.71 1246.85,1161.87 1317.32,1161.87 1319.29,1163.84 U3.5@1319.29,1167.24 ; R29.2@1300.76,196.42 1305.01,196.42 1378.59,270 ; LED1.1@1422.94,470.26 1430.6,462.6 1430.6,455.1 1483.44,402.26 1483.44,285.24 1468.19,270 1378.59,270 ; 155,449.57 155,185 220,120 510.77,120 560,169.23 v1(560,200) 588.83,228.83 1129.09,228.83 1170.26,270 ; 155,449.57 155,945 ; 155,945 155,1375 183.58,1403.58 I2C.1@239.45,1403.58 368.34,1403.58 ; 1170.26,270 1378.59,270
  Bottom Layer w10: v1@561.85,198.15 575.03,198.15 589.49,183.68 589.49,152 U1.24@590.49,151 ; U1.49@905.45,448 905.45,384.08 949.45,340.08 1239.72,340.08 1255.34,324.46 v1(1255.34,270.6)
  Bottom Layer w19.68: v1(334.78,980) 379.63,980 387.06,987.43 RT1.2@394.72,979.77
+5.0V: C30.1 C32.1 L1.2 R3.1 R9.1 R10.1 U3.1 U3.3 | length 2066.1
  Top Layer w23.62: v1(776.31,1184.56) 776.31,1169.96 R3.1@793.52,1152.75 ; U3.1@1320.4,1071.65 v1(1320.4,985) C30.1@1321.5,985 ; C32.1@1394.09,985 U3.3@1394.09,1064.13
  Top Layer w39.37: C30.1@1321.5,985 C32.1@1394.09,985 ; C32.1@1404.98,988.8 C32.1@1413.89,979.9 ; C32.1@1413.33,976.1 1545,844.43 v1(1545,615) v1(1545,588.75) v1(1545,562.5) v1(1545,536.25) v1@1545,512.29
  SIGNAL w23.62: v1(776.31,1184.56) 1015.54,1184.56 1215.1,985 v1(1320.4,985)
  Bottom Layer w10: R10.1@1367.57,110 1378.31,120.75 1410.3,120.75 1441.56,152 1490.91,152 1517.25,178.33 R9.1@1521.5,178.33 1525.75,178.33 1555,207.58 1555,384.21 L1.2@1508.9,430.31
  Bottom Layer w39.37: L1.2@1508.9,469.69 1545,505.79 v1(1545,510) v1(1545,536.25) v1(1545,562.5) v1(1545,588.75) v1(1545,615)
AH: U1.17 U2.29 | length 996.5
  Top Layer w10: v1@651.42,776.02 v1@652.48,776.02 ; v1@651.42,779.18 675.74,803.5 708.88,803.5 717.85,794.53 U2.29@763.69,794.53
  SIGNAL w10: v1@652.48,780.64 684.92,748.2 684.92,655.61 762,578.53 762,466.34 647.87,352.21 647.87,217.13 728.29,136.71 v1(728.29,94.11)
  Bottom Layer w10: v1(728.29,94.11) U1.17@728.29,151
  other v1: 651.42,780.64
AL: U1.18 U2.17 | length 1543.5
  Top Layer w10: v1@863.97,818.14 894.9,818.14 959.54,882.78 959.54,931.32 U2.17@960.54,932.32
  SIGNAL w10: v1(709.11,109.11) 709.11,85.89 723.78,71.22 744.24,71.22 792.35,119.33 1045,119.33 1115.67,190 1115.67,755.75 1055.14,816.28 v1(862.11,816.28)
  Bottom Layer w10: U1.18@708.6,151 708.86,150.74 v1@708.86,109.37
BH: U1.19 U2.30 | length 955
  Top Layer w10: v1@652.48,754.59 675.83,777.93 687.06,789.17 702.94,789.17 717.27,774.84 U2.30@763.69,774.84
  SIGNAL w10: v1(651.42,754.59) 652.48,754.59 670.59,736.48 670.59,649.68 742.11,578.16 742.11,466.71 633.54,358.14 633.54,211.2 689.78,154.95 v1(689.78,94.11)
  Bottom Layer w10: U1.19@688.92,151 689.35,150.57 v1@689.35,94.55
BL: U1.20 U2.18 | length 1608.4
  Top Layer w10: v1@863.97,846.28 897.29,846.28 939.85,888.84 939.85,931.32 U2.18@940.85,932.32
  SIGNAL w10: v1(668.78,109.11) 668.78,85.41 697.31,56.88 750.17,56.88 798.29,105 1050.94,105 1130,184.06 1130,761.69 1047.26,844.43 v1(862.11,844.43)
  Bottom Layer w10: v1@669.01,109.34 669.01,150.78 U1.20@669.23,151
CH: U1.21 U2.31 | length 907.1
  Top Layer w10: v1(651.42,728.54) 689.11,728.54 715.73,755.16 U2.31@763.69,755.16
  SIGNAL w10: v1@649.36,94.14 649.36,170.15 615.02,204.49 615.02,359.89 727.78,472.65 727.78,572.22 651.42,648.58 v1(651.42,728.54)
  Bottom Layer w10: v1@649.44,94.22 649.44,150.89 U1.21@649.55,151
  other v1: 649.33,94.11
CL: U1.22 U2.19 | length 1709.8
  Top Layer w10: v1(901.97,979.13) 920.17,960.93 920.17,933.32 U2.19@921.17,932.32
  SIGNAL w10: v1(630.18,109.11) 630.16,74.19 661.8,42.55 759.55,42.55 807.67,90.67 1056.87,90.67 1145,178.8 1145,771.42 1090,826.42 1090,949.73 1060.61,979.13 v1(901.97,979.13)
  Bottom Layer w10: U1.22@630.02,150.84 630.02,109.27 v1(630.18,109.11)
DC_CAL: U1.12 U2.43 | length 642.2
  Top Layer w10: v1(940.85,505) U2.43@940.85,597.68
  SIGNAL w10: v1(826.71,190) 826.71,177.35 854.06,150 915.27,150 980,214.73 980,465.85 v1(940.85,505)
  Bottom Layer w10: U1.12@826.71,151 v1(826.71,190)
DCBUS: C3.1 C4.1 C17.2 E2.1 E3.1 JP1.1 Q1.D Q2.D Q3.D U1.29 U1.53 U1.54 | length 2403.6
  Bottom Layer w10: E3.1@249.33,500 254.76,500 254.76,477.42 C17.2@337.18,395 ; C17.2@342.18,395 347.18,390 483.07,390 510.75,417.68 U1.29@510.75,447 ; U1.53@984.19,448 985,448.81 985,577.2 1003.88,558.33 U1.54@1003.88,448
  Bottom Layer w62.99: 1410,740 JP1.1@1410,1320
  Bottom Layer w66.93: v1@125,770 132.19,770 ; 295.74,606.46 555,606.46 854.06,606.46 883.32,577.2 985,577.2 1247.2,577.2 1410,740
  other v1: 185,465 213.19,465 185,487.5 213.19,487.5 185,510 213.19,510 1060,572.22 1080,572.22 1060,595 1080,595 915.21,727.13 940.85,727.13 92.83,728.54 120,728.54 92.83,749.27 120,749.27 915,750 940.85,750 92.83,770 120,770
DGND: C20.2 C21.1 C22.2 C23.1 C24.1 C25.1 C26.1 C27.1 C28.1 C29.2 C30.2 C31.2 FB1.2 I2C.4 R27.1 R30.2 SW1.1 SW2.1 SWD1.4 U2.8 U2.23 U2.47 U3.2 UART1.4 | length 5419.4
  Top Layer w10: UART1.4@239.45,221.42 205.98,221.42 174.17,253.23 174.17,352.41 191.76,370 289.02,370 396.5,477.48 C25.1@396.5,488.26 391.5,488.26 381.5,498.26 381.5,538.5 250,670 250,713.37 SWD1.4@239.45,723.92 205.98,723.92 174.17,755.73 174.17,854.91 189.27,870 338.82,870 381.5,912.68 381.5,969.13 391.5,979.13 345.63,1025 255.67,1025 225,1055.67 225,1215.67 I2C.4@235.75,1226.42 ; I2C.4@239.45,1226.42 I2C.4@235.75,1226.42 ; C26.1@688.5,1080 685,1083.5 652.01,1083.5 360.51,1375 185,1375 174.17,1364.17 174.17,1258.23 205.98,1226.42 I2C.4@235.75,1226.42 ; SW1.1@967.68,123.9 967.68,110.12 978.43,99.37 1204.14,99.37 1223.51,80 1276.2,80 1295.57,99.37 1406.65,99.37 1417.4,110.12 SW2.1@1417.4,123.9 ; R27.1@1040.75,385 1051.5,395.75 1051.5,400 1066.5,415 1066.5,508.5 1019.59,555.41 U2.47@1019.59,597.68 1019.59,738.8 1074.32,793.53 1097.33,793.53 U2.8@1098.33,794.53 1158.19,794.53 1217.17,853.51 1309.06,853.51 1319.06,863.51 C22.2@1319.06,868.51
  Top Layer w19.68: C29.2@1241.69,1083.5 1241.69,1085.83 1246.85,1090.98 1284.95,1090.98 1313.96,1120 1375,1120 ; C29.2@1245.1,1085.1 1245.1,988.4 C30.2@1248.5,985 1252.1,981.4 1252.1,940.47 C22.2@1319.06,873.51 ; U3.2@1356.69,1072.76 1356.69,1101.69 1375,1120 ; SW2.1@1417.4,123.9 1417.4,137.68 1423.31,143.58 1464.85,143.58 C24.1@1517.69,196.42 ; R30.2@1473.19,1233.26 1477.44,1233.26 1515,1195.7 1515,1136.81 1466.69,1088.5 1435.19,1120 1375,1120
  Top Layer w31.5: C22.2@1319.06,868.51 1464.69,868.51 1503.19,830 1503.19,663.45 1484.74,645 C20.2@1319.06,645 1319.06,549 1320.35,547.72 FB1.2@1320.35,345.85
  other v1: 459.2,73.66 435,84.17 270,90 405,90 455,155 380,186.67 410,186.67 440,186.67 380,245 410,245 440,245 471.43,245 500,245 380,270 410,270.26 440.31,270.26 500,270 471.43,270.6 35,275 67.5,275 100,275 35,331.86 67.5,331.86 100,331.86 35,390 67.5,390 100,390 310,1375 345,1375 770,1410.93 817.99,1410.93 861.54,1410.93 909.53,1410.93 957.5,1410.93 1005.46,1410.93 770,1439.47 817.96,1439.47 861.54,1439.47 909.51,1439.47 957.47,1439.47 1005.43,1439.47 770,1525 817.99,1525 861.54,1525 909.53,1525 957.5,1525 1005.46,1525 770,1553.54 817.96,1553.54 861.54,1553.54 909.51,1553.54 957.47,1553.54 1005.43,1553.54
EN_GATE: U1.16 U2.40 | length 1438
  Top Layer w10: v1@863.04,789.07 881.8,770.32 U2.40@881.8,597.68
  SIGNAL w10: v1(747.94,109.11) 772.49,133.66 1038.66,133.66 1100,195 1100,751.16 1063.01,788.14 v1(862.11,788.14)
  Bottom Layer w10: v1@747.95,109.13 U1.16@747.97,151
ENCA: MOTOR1.1 R6.2 U2.16 | length 535.5
  Top Layer w10: U2.16@980.22,932.32 981.22,933.32 981.22,986.22 1035,1040 1035,1096.7 1053.3,1115 1103.5,1115 1140,1151.5 1140,1185 1103.5,1221.5 1064.25,1221.5 R6.2@1060,1217.25 ; R6.2@1060,1221.5 MOTOR1.1@1060,1311.81
ENCB: MOTOR1.2 R5.2 U2.41 | length 2066.3
  Top Layer w10: v1(530,385) 797.58,385 901.48,488.9 U2.41@901.48,597.68 ; MOTOR1.2@989.45,1320 989.45,1225.43 R5.2@993.38,1221.5
  SIGNAL w10: v1(530,385) 530,538.67 334.47,734.2 334.47,930.53 678.93,1275 944.45,1275 MOTOR1.2@989.45,1320
ENCZ: MOTOR1.3 R4.2 U2.15 | length 998.5
  Top Layer w10: MOTOR1.3@910.71,1320 955.71,1365 1007.87,1365 1067.87,1425 1139.24,1425 1179.64,1384.6 1179.64,1082.94 1152.36,1055.67 1075.67,1055.67 1000.91,980.91 1000.91,933.32 U2.15@999.91,932.32 ; MOTOR1.3@916.01,1314.7 926.76,1303.95 R4.2@926.76,1221.5
GH_A: R11.2 U1.47 | length 992.5
  Top Layer w10: v1@440,370 v1(440.31,370) 498.97,428.67 818.67,428.67 864.23,474.23 864.23,493.15 v1(866.08,495) v1@866.08,492.38
  SIGNAL w10: v1(355,658.47) 490,523.47 490,414.69 445.31,370 v1(440.31,370) v1@440,370
  Bottom Layer w10: v1(355,658.47) 355,689.39 380,714.39 384.25,714.39 R11.2@395,725.13 ; U1.47@866.08,448 v1(866.08,495)
GH_B: R12.2 U1.42 | length 335.4
  SIGNAL w10: v1(725,670) 726,670 792.35,603.65 792.35,455.96 770.3,433.91 v1(770.3,409.49)
  Bottom Layer w10: U1.42@767.66,448 768.66,447 v1@768.66,411.14
GH_C: R13.2 U1.37 | length 1528.3
  SIGNAL w10: v1(669.12,495) 669.12,521.15 549.33,640.94 549.33,940.94 681.15,1072.76 1007.51,1072.76 1118.66,961.61 1118.66,841.3 1184.13,775.83 1192.58,767.42 v1(1192.58,716.23)
  Bottom Layer w10: v1(669.12,495) 669.17,494.94 U1.37@669.17,448.06 ; R13.2@1158.14,729.22 1171.13,716.23 v1(1192.58,716.23)
GL_A: R16.2 U1.45 | length 1364.9
  Top Layer w10: v1(440.31,450) 460.31,470 801.71,470 v1(826.71,495)
  SIGNAL w10: v1(395,1154.65) 395,1070.7 166.34,842.04 166.34,778.77 440.31,504.8 v1(440.31,450)
  Bottom Layer w10: U1.45@826.71,448 v1(826.71,495)
GL_B: R17.2 U1.40 | length 468.1
  Bottom Layer w10: R17.2@342.18,325 352.92,335.75 562.01,335.75 606.27,380 713.29,380 725.77,392.48 725.77,414.55 727.29,416.07 727.29,447 U1.40@728.29,448
GL_C: R18.2 U1.35 | length 1580.9
  SIGNAL w10: v1(629.86,495) 629.35,495.51 629.35,520.38 392.96,756.77 392.96,907.96 701.34,1216.34 1013.66,1216.34 1190,1040 v1(1215,1040)
  Bottom Layer w10: U1.35@629.86,448 v1(629.86,495)
GND: C1.2 C2.2 C3.2 C4.2 C5.2 C6.1 C10.2 C13.1 C14.1 C15.2 C16.1 C17.1 C18.2 C19.2 C32.2 D1.1 E2.2 E3.2 FB1.1 JP1.2 MOTOR1.4 Q4.S R1.2 R8.1 R14.2 R15.1 R21.1 R22.1 U1.8 U1.28 U1.30 U1.32 U1.44 U1.57 | length 2171.6
  Top Layer w8: JP1.2@1331.26,1320 JP1.2@1334.72,1320
  Top Layer w10: v1(337.18,1088.83) 433.41,1088.83 552.25,970 R1.2@556.5,970 C1.2@556.5,905 ; v1(1501.08,1027.88) 1501.08,984.06 C32.2@1504.56,980.57
  Top Layer w23.62: v1(1417.4,300) FB1.1@1382.38,335 v1(1417.4,370)
  Bottom Layer w8: E3.2@40.67,500 43.66,502.99 56.99,502.99 75,521 v1(75,525) ; v1(130,215) 133.17,215 161.5,186.67 C19.2@166.5,186.67 ; C18.2@166.5,50 171.5,45 v1(215,45) 264.18,45 C10.2@269.18,50 ; C15.2@269.18,186.67 274.18,186.67 305.04,217.53 v1(305.04,218.23) 302.8,220.47 302.8,226.37 274.18,255 C13.1@269.18,255 264.18,255 253.18,266 253.18,271 217.03,307.15 217.03,347.85 264.18,395 C17.1@269.18,395 ; v1(475,175) 509.75,175 511.75,173 U1.28@511.75,151 ; v1(509.75,502.99) 529.44,483.31 529.44,450 U1.30@531.44,448 ; U1.32@570.81,448 571.43,447.38 v1(571.43,405) ; U1.57@777.5,299.5 807.03,329.03 U1.44@807.03,448 ; U1.57@886,253 905.45,233.55 U1.8@905.45,151 ; C3.2@1127.89,493.5 1205.31,493.5 1210,488.81 1210,429.11 C6.1@1205.89,425 ; C5.2@1136.59,246.67 1141.59,246.67 1152.59,257.67 1152.59,262.25 1205.33,315 v1(1209.59,315) ; v1(1180,135) 1180,134.59 1204.59,110 C2.2@1209.59,110
  Bottom Layer w10: C16.1@1246.52,1405 cw(c1251.52,1405) 1251.52,1410 1331.31,1410 ; C14.1@1343.42,1034.44 cw(c1343.42,1029.24) 1348.62,1029.24 v1(1348.62,937.12) ; R14.2@1367.57,178.33 1371.82,178.33 1413.49,220 v1(1415,220) ; v1(1460,610) 1505,655 E2.2@1529.33,655 ; R15.1@1521.5,110 1530,101.5 v1(1530,77.66)
  Bottom Layer w23.62: v1(1417.4,300) 1480.12,300 D1.1@1495.12,285
  other v1: 1210,493.5 1479.77,1024.08 1521.27,1024.08 1480,1045 1500.75,1045 1521.5,1045 258.7,1088.83 258.7,1115.38 337.18,1115.38 258.7,1141.92 337.18,1141.92 258.7,1168.46 337.18,1168.46 258.7,1195 337.18,1195 1480.23,1301.11 1500.98,1301.11 1521.73,1301.11 1480,1324.05 1500.75,1324.05 1521.5,1324.05 1389.25,1405 1410,1405 1430.75,1405 1389.25,1425 1410,1425 1430.75,1425 1389.25,1445.74 1410,1445.74 1430.75,1445.74 1389.25,1467.13 1410,1467.13 1430.75,1467.13 1389.25,1490 1410,1490 1430.75,1490
I2C_SCL: I2C.3 U2.21 | length 841.5
  Top Layer w10: I2C.3@239.45,1285.47 250.2,1274.72 408.69,1274.72 798.25,885.16 858.23,885.16 880.8,907.73 880.8,931.32 U2.21@881.8,932.32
